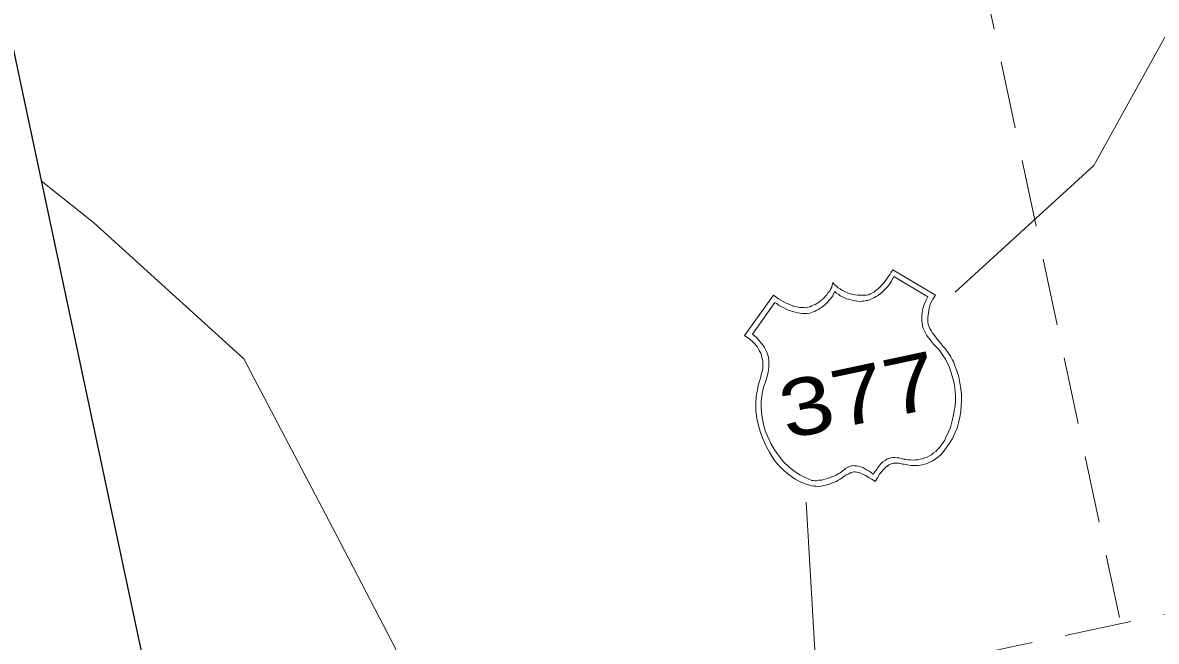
# Model space of a CAD drawing. Extents: x 2357218 to 2371708, y 6973728 to 6980157.
# Drawn here: x 2357307.6 to 2357408.8, y 6974509.8 to 6974565 of the extents above; entities that cross this region are included whole.
import ezdxf

# ---------------------------------------------------------------- set-up
doc = ezdxf.new("R2010")
doc.units = 0
doc.header["$LTSCALE"] = 2
doc.linetypes.add('MEDIUM_DASHED', pattern=[4.5, 3, -1.5])
doc.layers.add('62', color=7, linetype='Continuous', lineweight=13)
doc.layers.add('63', color=7, linetype='Continuous', lineweight=13)

msp = doc.modelspace()

# ---------------------------------------------------------------- linework, layer by layer
at = {"layer": '62', "linetype": 'MEDIUM_DASHED'}
for p, q in [((2357366.864, 6974693.567), (2357405.498, 6974511.924)), ((2357321.423, 6974493.477), (2357761.192, 6974586.953))]:
    msp.add_line(p, q, dxfattribs=at)
at = {"layer": '62'}
msp.add_line((2357403.224, 6974552.273), (2357390.835, 6974540.968), dxfattribs=at)
at = {"layer": '62', "lineweight": 25}
msp.add_lwpolyline([(2357242.867, 6974863.05), (2357339.603, 6974407.945), (2357779.37, 6974501.42), (2357682.634, 6974956.528)], dxfattribs=at)
at = {"layer": '62'}
for points in [[(2357432.423, 6974601.035), (2357426.152, 6974591.262), (2357421.824, 6974582.844), (2357411.809, 6974567.829), (2357403.224, 6974552.273)], [(2357309.219, 6974550.9), (2357313.892, 6974547.2), (2357327.315, 6974535.032), (2357335.518, 6974519.384), (2357342.091, 6974506.75), (2357351.934, 6974500.263), (2357369.659, 6974490.04), (2357379.731, 6974485.624), (2357395.823, 6974478.418), (2357410.579, 6974464.416)], [(2357372.035, 6974537.087), (2357374.604, 6974540.692), (2357374.818, 6974540.552), (2357375.062, 6974540.374), (2357375.271, 6974540.259), (2357375.48, 6974540.141), (2357375.689, 6974540.024), (2357375.916, 6974539.934), (2357376.12, 6974539.841), (2357376.325, 6974539.745), (2357376.519, 6974539.694), (2357376.714, 6974539.645), (2357376.928, 6974539.599), (2357377.115, 6974539.593), (2357377.322, 6974539.591), (2357377.486, 6974539.58), (2357377.684, 6974539.62), (2357377.882, 6974539.663), (2357378.005, 6974539.736), (2357378.15, 6974539.813), (2357378.322, 6974539.873), (2357378.489, 6974539.953), (2357378.646, 6974540.078), (2357378.808, 6974540.182), (2357378.942, 6974540.301), (2357379.1, 6974540.426), (2357379.249, 6974540.598), (2357379.38, 6974540.742), (2357379.5, 6974540.928), (2357379.631, 6974541.071), (2357379.732, 6974541.252), (2357379.806, 6974541.429), (2357379.857, 6974541.623), (2357379.91, 6974541.819), (2357380.057, 6974541.665), (2357380.225, 6974541.518), (2357380.372, 6974541.365), (2357380.557, 6974541.266), (2357380.721, 6974541.139), (2357380.924, 6974541.046), (2357381.129, 6974540.95), (2357381.305, 6974540.873), (2357381.501, 6974540.824), (2357381.703, 6974540.751), (2357381.914, 6974540.728), (2357382.103, 6974540.697), (2357382.335, 6974540.702), (2357382.497, 6974540.689), (2357382.725, 6974540.693), (2357382.928, 6974540.712), (2357383.082, 6974540.745), (2357383.252, 6974540.805), (2357383.397, 6974540.88), (2357383.589, 6974540.968), (2357383.723, 6974541.088), (2357383.88, 6974541.214), (2357384.016, 6974541.335), (2357384.169, 6974541.483), (2357384.298, 6974541.625), (2357384.469, 6974541.8), (2357384.596, 6974541.965), (2357384.737, 6974542.154), (2357384.861, 6974542.343), (2357385.019, 6974542.561), (2357385.12, 6974542.742), (2357385.258, 6974542.955), (2357389.073, 6974540.708), (2357388.851, 6974540.338), (2357388.635, 6974539.949), (2357388.515, 6974539.531), (2357388.443, 6974539.123), (2357388.389, 6974538.721), (2357388.398, 6974538.354), (2357388.432, 6974538.086), (2357388.502, 6974537.871), (2357388.557, 6974537.721), (2357388.687, 6974537.541), (2357388.788, 6974537.381), (2357388.924, 6974537.177), (2357389.082, 6974536.979), (2357389.24, 6974536.784), (2357389.401, 6974536.566), (2357389.584, 6974536.351), (2357389.772, 6974536.113), (2357389.956, 6974535.901), (2357390.148, 6974535.641), (2357390.309, 6974535.424), (2357390.448, 6974535.201), (2357390.571, 6974534.951), (2357390.71, 6974534.726), (2357390.784, 6974534.488), (2357390.995, 6974533.937), (2357391.15, 6974533.417), (2357391.262, 6974532.889), (2357391.33, 6974532.352), (2357391.394, 6974531.835), (2357391.39, 6974531.306), (2357391.379, 6974530.822), (2357391.327, 6974530.303), (2357391.252, 6974529.803), (2357391.129, 6974529.294)], [(2357390.148, 6974528.28), (2357390.272, 6974528.562), (2357390.409, 6974528.89), (2357390.515, 6974529.258), (2357390.605, 6974529.597), (2357390.679, 6974530.005), (2357390.755, 6974530.411), (2357390.828, 6974530.817), (2357390.85, 6974531.261), (2357390.849, 6974531.697), (2357390.82, 6974532.151), (2357390.788, 6974532.628), (2357390.688, 6974533.089), (2357390.544, 6974533.565), (2357390.408, 6974533.973), (2357390.288, 6974534.338), (2357390.125, 6974534.671), (2357389.967, 6974534.982), (2357389.766, 6974535.284), (2357389.572, 6974535.543), (2357389.399, 6974535.806), (2357389.191, 6974536.038), (2357388.958, 6974536.264), (2357388.8, 6974536.459), (2357388.618, 6974536.673), (2357388.457, 6974536.893), (2357388.294, 6974537.112), (2357388.177, 6974537.342), (2357388.059, 6974537.57), (2357387.958, 6974537.824), (2357387.893, 6974538.132), (2357387.867, 6974538.474), (2357387.864, 6974538.817), (2357387.881, 6974539.167), (2357387.944, 6974539.524), (2357388.075, 6974539.873), (2357388.213, 6974540.203), (2357388.395, 6974540.54), (2357385.363, 6974542.357), (2357385.246, 6974542.148), (2357385.146, 6974541.965), (2357385.026, 6974541.78), (2357384.904, 6974541.593), (2357384.758, 6974541.423), (2357384.608, 6974541.253), (2357384.457, 6974541.107), (2357384.302, 6974540.96), (2357384.123, 6974540.83), (2357383.971, 6974540.682), (2357383.786, 6974540.572), (2357383.642, 6974540.495), (2357383.459, 6974540.389), (2357383.309, 6974540.333), (2357383.18, 6974540.284), (2357383.03, 6974540.229), (2357382.874, 6974540.216), (2357382.674, 6974540.174), (2357382.493, 6974540.16), (2357382.312, 6974540.145), (2357382.101, 6974540.168), (2357381.932, 6974540.202), (2357381.72, 6974540.227), (2357381.525, 6974540.278), (2357381.352, 6974540.333), (2357381.134, 6974540.378), (2357380.958, 6974540.455), (2357380.775, 6974540.555), (2357380.576, 6974540.628), (2357380.434, 6974540.758), (2357380.247, 6974540.878), (2357380.076, 6974541.026), (2357379.982, 6974540.823), (2357379.906, 6974540.646), (2357379.775, 6974540.501), (2357379.672, 6974540.341), (2357379.557, 6974540.227), (2357379.449, 6974540.089), (2357379.295, 6974539.94), (2357379.202, 6974539.829), (2357379.042, 6974539.726), (2357378.906, 6974539.605), (2357378.763, 6974539.527), (2357378.622, 6974539.429), (2357378.47, 6974539.375), (2357378.334, 6974539.276), (2357378.163, 6974539.215), (2357378.013, 6974539.161), (2357377.841, 6974539.103), (2357377.62, 6974539.056), (2357377.435, 6974539.062), (2357377.206, 6974539.06), (2357376.995, 6974539.083), (2357376.755, 6974539.124), (2357376.539, 6974539.171), (2357376.339, 6974539.244), (2357376.116, 6974539.312), (2357375.871, 6974539.397), (2357375.67, 6974539.469), (2357375.483, 6974539.589), (2357375.252, 6974539.703), (2357375.065, 6974539.822)], [(2357374.742, 6974540.054), (2357372.723, 6974537.21), (2357373.083, 6974536.919), (2357373.361, 6974536.585), (2357373.602, 6974536.314), (2357373.801, 6974536.036), (2357373.959, 6974535.725), (2357374.067, 6974535.425), (2357374.169, 6974535.169), (2357374.187, 6974534.874), (2357374.202, 6974534.578), (2357374.192, 6974534.3), (2357374.165, 6974533.992), (2357374.112, 6974533.706), (2357374.052, 6974533.44), (2357373.953, 6974533.143), (2357373.854, 6974532.87), (2357373.754, 6974532.572), (2357373.59, 6974531.937), (2357373.523, 6974531.281), (2357373.495, 6974530.653), (2357373.569, 6974529.98), (2357373.687, 6974529.316), (2357373.845, 6974528.679), (2357374.095, 6974528.044), (2357374.378, 6974527.46), (2357374.708, 6974526.888), (2357375.106, 6974526.327), (2357375.506, 6974525.837), (2357375.973, 6974525.383), (2357376.445, 6974525.001), (2357376.955, 6974524.65), (2357377.495, 6974524.397), (2357378.047, 6974524.168), (2357378.163, 6974524.17), (2357378.288, 6974524.128), (2357378.444, 6974524.138), (2357378.622, 6974524.174), (2357378.779, 6974524.185), (2357378.938, 6974524.197), (2357379.116, 6974524.235), (2357379.307, 6974524.299), (2357379.481, 6974524.358), (2357379.655, 6974524.395), (2357379.823, 6974524.477), (2357379.993, 6974524.537), (2357380.16, 6974524.617), (2357380.305, 6974524.695), (2357380.445, 6974524.794), (2357380.572, 6974524.842), (2357380.707, 6974524.965), (2357380.826, 6974525.059), (2357380.944, 6974525.152), (2357381.063, 6974525.245), (2357381.229, 6974525.327), (2357381.334, 6974525.374), (2357381.479, 6974525.45), (2357381.655, 6974525.487), (2357381.817, 6974525.477), (2357382.026, 6974525.474), (2357382.216, 6974525.445), (2357382.394, 6974525.368), (2357382.643, 6974525.284), (2357382.909, 6974525.11), (2357383.218, 6974524.946), (2357383.517, 6974524.734), (2357383.765, 6974525.085), (2357383.978, 6974525.384), (2357384.159, 6974525.607), (2357384.369, 6974525.812), (2357384.57, 6974525.946), (2357384.732, 6974526.049), (2357384.922, 6974526.135), (2357385.119, 6974526.179), (2357385.297, 6974526.216), (2357385.46, 6974526.204), (2357385.65, 6974526.175), (2357385.835, 6974526.169), (2357386.03, 6974526.119), (2357386.225, 6974526.066), (2357386.41, 6974526.061), (2357386.631, 6974525.993), (2357386.84, 6974525.992), (2357387.075, 6974525.971), (2357387.277, 6974525.991), (2357387.478, 6974526.011), (2357387.699, 6974526.059), (2357387.92, 6974526.105), (2357388.115, 6974526.169), (2357388.329, 6974526.239), (2357388.534, 6974526.35), (2357388.724, 6974526.438), (2357388.894, 6974526.613), (2357389.094, 6974526.747), (2357389.244, 6974526.916), (2357389.435, 6974527.094), (2357389.595, 6974527.314), (2357389.751, 6974527.552), (2357389.896, 6974527.746), (2357389.999, 6974528.02), (2357390.148, 6974528.28)], [(2357375.065, 6974539.822), (2357374.901, 6974539.95), (2357374.742, 6974540.054)], [(2357372.859, 6974536.455), (2357372.495, 6974536.77), (2357372.035, 6974537.087)], [(2357391.129, 6974529.294), (2357390.999, 6974528.829), (2357390.795, 6974528.373), (2357390.596, 6974527.917), (2357390.316, 6974527.49), (2357390.039, 6974527.063), (2357389.736, 6974526.653), (2357389.547, 6974526.451), (2357389.373, 6974526.3), (2357389.154, 6974526.139), (2357388.954, 6974526.002), (2357388.775, 6974525.874), (2357388.558, 6974525.805), (2357388.33, 6974525.687), (2357388.137, 6974525.622), (2357387.922, 6974525.555), (2357387.697, 6974525.528), (2357387.494, 6974525.51), (2357387.292, 6974525.489), (2357387.057, 6974525.509), (2357386.898, 6974525.498), (2357386.686, 6974525.52), (2357386.491, 6974525.573), (2357386.323, 6974525.606), (2357386.14, 6974525.611), (2357385.966, 6974525.667), (2357385.8, 6974525.7), (2357385.638, 6974525.69), (2357385.475, 6974525.7), (2357385.289, 6974525.708), (2357385.117, 6974525.649), (2357384.951, 6974525.567), (2357384.789, 6974525.464), (2357384.613, 6974525.311), (2357384.46, 6974525.162), (2357384.257, 6974524.935), (2357384.073, 6974524.713), (2357383.91, 6974524.402), (2357383.683, 6974524.056), (2357383.387, 6974524.267), (2357383.097, 6974524.436), (2357382.853, 6974524.613), (2357382.625, 6974524.704), (2357382.417, 6974524.821), (2357382.224, 6974524.872), (2357382.055, 6974524.906), (2357381.891, 6974524.917), (2357381.777, 6974524.916), (2357381.601, 6974524.879), (2357381.49, 6974524.853), (2357381.351, 6974524.756), (2357381.223, 6974524.704), (2357381.096, 6974524.656), (2357380.962, 6974524.535), (2357380.813, 6974524.458), (2357380.72, 6974524.368), (2357380.553, 6974524.288), (2357380.391, 6974524.182), (2357380.231, 6974524.08), (2357380.036, 6974524.014), (2357379.864, 6974523.958), (2357379.679, 6974523.849), (2357379.488, 6974523.785), (2357379.267, 6974523.737), (2357379.091, 6974523.701), (2357378.87, 6974523.654), (2357378.623, 6974523.622), (2357378.411, 6974523.649), (2357378.183, 6974523.645), (2357377.938, 6974523.708), (2357377.696, 6974523.771), (2357377.123, 6974523.972), (2357376.549, 6974524.289), (2357376.011, 6974524.656), (2357375.508, 6974525.078), (2357375.039, 6974525.553), (2357374.637, 6974526.042), (2357374.284, 6974526.612), (2357373.951, 6974527.207), (2357373.684, 6974527.819), (2357373.459, 6974528.437), (2357373.259, 6974529.063), (2357373.123, 6974529.701), (2357373.047, 6974530.374), (2357373.032, 6974530.993), (2357373.073, 6974531.668), (2357373.173, 6974532.265), (2357373.217, 6974532.502), (2357373.274, 6974532.768), (2357373.359, 6974533.016), (2357373.464, 6974533.291), (2357373.517, 6974533.58), (2357373.592, 6974533.872), (2357373.664, 6974534.188), (2357373.67, 6974534.487), (2357373.647, 6974534.807), (2357373.577, 6974535.136), (2357373.508, 6974535.468), (2357373.327, 6974535.774), (2357373.142, 6974536.104), (2357372.859, 6974536.455)], [(2357377.519, 6974522.215), (2357378.302, 6974509.018), (2357377.771, 6974495.492), (2357368.736, 6974481.608), (2357356.967, 6974466.526), (2357344.304, 6974446.557), (2357333.83, 6974435.105)]]:
    msp.add_lwpolyline(points, dxfattribs=at)
at = {"layer": '63', "linetype": 'MEDIUM_DASHED'}
for p, q in [((2357366.864, 6974693.567), (2357405.498, 6974511.924)), ((2357321.423, 6974493.477), (2357761.192, 6974586.953))]:
    msp.add_line(p, q, dxfattribs=at)
at = {"layer": '63'}
msp.add_line((2357403.224, 6974552.273), (2357390.835, 6974540.968), dxfattribs=at)
at = {"layer": '63', "lineweight": 25}
msp.add_lwpolyline([(2357242.867, 6974863.05), (2357339.603, 6974407.945), (2357779.37, 6974501.42), (2357682.634, 6974956.528)], dxfattribs=at)
at = {"layer": '63'}
for points in [[(2357432.423, 6974601.035), (2357426.152, 6974591.262), (2357421.824, 6974582.844), (2357411.809, 6974567.829), (2357403.224, 6974552.273)], [(2357309.219, 6974550.9), (2357313.892, 6974547.2), (2357327.315, 6974535.032), (2357335.518, 6974519.384), (2357342.091, 6974506.75), (2357351.934, 6974500.263), (2357369.659, 6974490.04), (2357379.731, 6974485.624), (2357395.823, 6974478.418), (2357410.579, 6974464.416)], [(2357372.035, 6974537.087), (2357374.604, 6974540.692), (2357374.818, 6974540.552), (2357375.062, 6974540.374), (2357375.271, 6974540.259), (2357375.48, 6974540.141), (2357375.689, 6974540.024), (2357375.916, 6974539.934), (2357376.12, 6974539.841), (2357376.325, 6974539.745), (2357376.519, 6974539.694), (2357376.714, 6974539.645), (2357376.928, 6974539.599), (2357377.115, 6974539.593), (2357377.322, 6974539.591), (2357377.486, 6974539.58), (2357377.684, 6974539.62), (2357377.882, 6974539.663), (2357378.005, 6974539.736), (2357378.15, 6974539.813), (2357378.322, 6974539.873), (2357378.489, 6974539.953), (2357378.646, 6974540.078), (2357378.808, 6974540.182), (2357378.942, 6974540.301), (2357379.1, 6974540.426), (2357379.249, 6974540.598), (2357379.38, 6974540.742), (2357379.5, 6974540.928), (2357379.631, 6974541.071), (2357379.732, 6974541.252), (2357379.806, 6974541.429), (2357379.857, 6974541.623), (2357379.91, 6974541.819), (2357380.057, 6974541.665), (2357380.225, 6974541.518), (2357380.372, 6974541.365), (2357380.557, 6974541.266), (2357380.721, 6974541.139), (2357380.924, 6974541.046), (2357381.129, 6974540.95), (2357381.305, 6974540.873), (2357381.501, 6974540.824), (2357381.703, 6974540.751), (2357381.914, 6974540.728), (2357382.103, 6974540.697), (2357382.335, 6974540.702), (2357382.497, 6974540.689), (2357382.725, 6974540.693), (2357382.928, 6974540.712), (2357383.082, 6974540.745), (2357383.252, 6974540.805), (2357383.397, 6974540.88), (2357383.589, 6974540.968), (2357383.723, 6974541.088), (2357383.88, 6974541.214), (2357384.016, 6974541.335), (2357384.169, 6974541.483), (2357384.298, 6974541.625), (2357384.469, 6974541.8), (2357384.596, 6974541.965), (2357384.737, 6974542.154), (2357384.861, 6974542.343), (2357385.019, 6974542.561), (2357385.12, 6974542.742), (2357385.258, 6974542.955), (2357389.073, 6974540.708), (2357388.851, 6974540.338), (2357388.635, 6974539.949), (2357388.515, 6974539.531), (2357388.443, 6974539.123), (2357388.389, 6974538.721), (2357388.398, 6974538.354), (2357388.432, 6974538.086), (2357388.502, 6974537.871), (2357388.557, 6974537.721), (2357388.687, 6974537.541), (2357388.788, 6974537.381), (2357388.924, 6974537.177), (2357389.082, 6974536.979), (2357389.24, 6974536.784), (2357389.401, 6974536.566), (2357389.584, 6974536.351), (2357389.772, 6974536.113), (2357389.956, 6974535.901), (2357390.148, 6974535.641), (2357390.309, 6974535.424), (2357390.448, 6974535.201), (2357390.571, 6974534.951), (2357390.71, 6974534.726), (2357390.784, 6974534.488), (2357390.995, 6974533.937), (2357391.15, 6974533.417), (2357391.262, 6974532.889), (2357391.33, 6974532.352), (2357391.394, 6974531.835), (2357391.39, 6974531.306), (2357391.379, 6974530.822), (2357391.327, 6974530.303), (2357391.252, 6974529.803), (2357391.129, 6974529.294)], [(2357390.148, 6974528.28), (2357390.272, 6974528.562), (2357390.409, 6974528.89), (2357390.515, 6974529.258), (2357390.605, 6974529.597), (2357390.679, 6974530.005), (2357390.755, 6974530.411), (2357390.828, 6974530.817), (2357390.85, 6974531.261), (2357390.849, 6974531.697), (2357390.82, 6974532.151), (2357390.788, 6974532.628), (2357390.688, 6974533.089), (2357390.544, 6974533.565), (2357390.408, 6974533.973), (2357390.288, 6974534.338), (2357390.125, 6974534.671), (2357389.967, 6974534.982), (2357389.766, 6974535.284), (2357389.572, 6974535.543), (2357389.399, 6974535.806), (2357389.191, 6974536.038), (2357388.958, 6974536.264), (2357388.8, 6974536.459), (2357388.618, 6974536.673), (2357388.457, 6974536.893), (2357388.294, 6974537.112), (2357388.177, 6974537.342), (2357388.059, 6974537.57), (2357387.958, 6974537.824), (2357387.893, 6974538.132), (2357387.867, 6974538.474), (2357387.864, 6974538.817), (2357387.881, 6974539.167), (2357387.944, 6974539.524), (2357388.075, 6974539.873), (2357388.213, 6974540.203), (2357388.395, 6974540.54), (2357385.363, 6974542.357), (2357385.246, 6974542.148), (2357385.146, 6974541.965), (2357385.026, 6974541.78), (2357384.904, 6974541.593), (2357384.758, 6974541.423), (2357384.608, 6974541.253), (2357384.457, 6974541.107), (2357384.302, 6974540.96), (2357384.123, 6974540.83), (2357383.971, 6974540.682), (2357383.786, 6974540.572), (2357383.642, 6974540.495), (2357383.459, 6974540.389), (2357383.309, 6974540.333), (2357383.18, 6974540.284), (2357383.03, 6974540.229), (2357382.874, 6974540.216), (2357382.674, 6974540.174), (2357382.493, 6974540.16), (2357382.312, 6974540.145), (2357382.101, 6974540.168), (2357381.932, 6974540.202), (2357381.72, 6974540.227), (2357381.525, 6974540.278), (2357381.352, 6974540.333), (2357381.134, 6974540.378), (2357380.958, 6974540.455), (2357380.775, 6974540.555), (2357380.576, 6974540.628), (2357380.434, 6974540.758), (2357380.247, 6974540.878), (2357380.076, 6974541.026), (2357379.982, 6974540.823), (2357379.906, 6974540.646), (2357379.775, 6974540.501), (2357379.672, 6974540.341), (2357379.557, 6974540.227), (2357379.449, 6974540.089), (2357379.295, 6974539.94), (2357379.202, 6974539.829), (2357379.042, 6974539.726), (2357378.906, 6974539.605), (2357378.763, 6974539.527), (2357378.622, 6974539.429), (2357378.47, 6974539.375), (2357378.334, 6974539.276), (2357378.163, 6974539.215), (2357378.013, 6974539.161), (2357377.841, 6974539.103), (2357377.62, 6974539.056), (2357377.435, 6974539.062), (2357377.206, 6974539.06), (2357376.995, 6974539.083), (2357376.755, 6974539.124), (2357376.539, 6974539.171), (2357376.339, 6974539.244), (2357376.116, 6974539.312), (2357375.871, 6974539.397), (2357375.67, 6974539.469), (2357375.483, 6974539.589), (2357375.252, 6974539.703), (2357375.065, 6974539.822)], [(2357374.742, 6974540.054), (2357372.723, 6974537.21), (2357373.083, 6974536.919), (2357373.361, 6974536.585), (2357373.602, 6974536.314), (2357373.801, 6974536.036), (2357373.959, 6974535.725), (2357374.067, 6974535.425), (2357374.169, 6974535.169), (2357374.187, 6974534.874), (2357374.202, 6974534.578), (2357374.192, 6974534.3), (2357374.165, 6974533.992), (2357374.112, 6974533.706), (2357374.052, 6974533.44), (2357373.953, 6974533.143), (2357373.854, 6974532.87), (2357373.754, 6974532.572), (2357373.59, 6974531.937), (2357373.523, 6974531.281), (2357373.495, 6974530.653), (2357373.569, 6974529.98), (2357373.687, 6974529.316), (2357373.845, 6974528.679), (2357374.095, 6974528.044), (2357374.378, 6974527.46), (2357374.708, 6974526.888), (2357375.106, 6974526.327), (2357375.506, 6974525.837), (2357375.973, 6974525.383), (2357376.445, 6974525.001), (2357376.955, 6974524.65), (2357377.495, 6974524.397), (2357378.047, 6974524.168), (2357378.163, 6974524.17), (2357378.288, 6974524.128), (2357378.444, 6974524.138), (2357378.622, 6974524.174), (2357378.779, 6974524.185), (2357378.938, 6974524.197), (2357379.116, 6974524.235), (2357379.307, 6974524.299), (2357379.481, 6974524.358), (2357379.655, 6974524.395), (2357379.823, 6974524.477), (2357379.993, 6974524.537), (2357380.16, 6974524.617), (2357380.305, 6974524.695), (2357380.445, 6974524.794), (2357380.572, 6974524.842), (2357380.707, 6974524.965), (2357380.826, 6974525.059), (2357380.944, 6974525.152), (2357381.063, 6974525.245), (2357381.229, 6974525.327), (2357381.334, 6974525.374), (2357381.479, 6974525.45), (2357381.655, 6974525.487), (2357381.817, 6974525.477), (2357382.026, 6974525.474), (2357382.216, 6974525.445), (2357382.394, 6974525.368), (2357382.643, 6974525.284), (2357382.909, 6974525.11), (2357383.218, 6974524.946), (2357383.517, 6974524.734), (2357383.765, 6974525.085), (2357383.978, 6974525.384), (2357384.159, 6974525.607), (2357384.369, 6974525.812), (2357384.57, 6974525.946), (2357384.732, 6974526.049), (2357384.922, 6974526.135), (2357385.119, 6974526.179), (2357385.297, 6974526.216), (2357385.46, 6974526.204), (2357385.65, 6974526.175), (2357385.835, 6974526.169), (2357386.03, 6974526.119), (2357386.225, 6974526.066), (2357386.41, 6974526.061), (2357386.631, 6974525.993), (2357386.84, 6974525.992), (2357387.075, 6974525.971), (2357387.277, 6974525.991), (2357387.478, 6974526.011), (2357387.699, 6974526.059), (2357387.92, 6974526.105), (2357388.115, 6974526.169), (2357388.329, 6974526.239), (2357388.534, 6974526.35), (2357388.724, 6974526.438), (2357388.894, 6974526.613), (2357389.094, 6974526.747), (2357389.244, 6974526.916), (2357389.435, 6974527.094), (2357389.595, 6974527.314), (2357389.751, 6974527.552), (2357389.896, 6974527.746), (2357389.999, 6974528.02), (2357390.148, 6974528.28)], [(2357375.065, 6974539.822), (2357374.901, 6974539.95), (2357374.742, 6974540.054)], [(2357372.859, 6974536.455), (2357372.495, 6974536.77), (2357372.035, 6974537.087)], [(2357391.129, 6974529.294), (2357390.999, 6974528.829), (2357390.795, 6974528.373), (2357390.596, 6974527.917), (2357390.316, 6974527.49), (2357390.039, 6974527.063), (2357389.736, 6974526.653), (2357389.547, 6974526.451), (2357389.373, 6974526.3), (2357389.154, 6974526.139), (2357388.954, 6974526.002), (2357388.775, 6974525.874), (2357388.558, 6974525.805), (2357388.33, 6974525.687), (2357388.137, 6974525.622), (2357387.922, 6974525.555), (2357387.697, 6974525.528), (2357387.494, 6974525.51), (2357387.292, 6974525.489), (2357387.057, 6974525.509), (2357386.898, 6974525.498), (2357386.686, 6974525.52), (2357386.491, 6974525.573), (2357386.323, 6974525.606), (2357386.14, 6974525.611), (2357385.966, 6974525.667), (2357385.8, 6974525.7), (2357385.638, 6974525.69), (2357385.475, 6974525.7), (2357385.289, 6974525.708), (2357385.117, 6974525.649), (2357384.951, 6974525.567), (2357384.789, 6974525.464), (2357384.613, 6974525.311), (2357384.46, 6974525.162), (2357384.257, 6974524.935), (2357384.073, 6974524.713), (2357383.91, 6974524.402), (2357383.683, 6974524.056), (2357383.387, 6974524.267), (2357383.097, 6974524.436), (2357382.853, 6974524.613), (2357382.625, 6974524.704), (2357382.417, 6974524.821), (2357382.224, 6974524.872), (2357382.055, 6974524.906), (2357381.891, 6974524.917), (2357381.777, 6974524.916), (2357381.601, 6974524.879), (2357381.49, 6974524.853), (2357381.351, 6974524.756), (2357381.223, 6974524.704), (2357381.096, 6974524.656), (2357380.962, 6974524.535), (2357380.813, 6974524.458), (2357380.72, 6974524.368), (2357380.553, 6974524.288), (2357380.391, 6974524.182), (2357380.231, 6974524.08), (2357380.036, 6974524.014), (2357379.864, 6974523.958), (2357379.679, 6974523.849), (2357379.488, 6974523.785), (2357379.267, 6974523.737), (2357379.091, 6974523.701), (2357378.87, 6974523.654), (2357378.623, 6974523.622), (2357378.411, 6974523.649), (2357378.183, 6974523.645), (2357377.938, 6974523.708), (2357377.696, 6974523.771), (2357377.123, 6974523.972), (2357376.549, 6974524.289), (2357376.011, 6974524.656), (2357375.508, 6974525.078), (2357375.039, 6974525.553), (2357374.637, 6974526.042), (2357374.284, 6974526.612), (2357373.951, 6974527.207), (2357373.684, 6974527.819), (2357373.459, 6974528.437), (2357373.259, 6974529.063), (2357373.123, 6974529.701), (2357373.047, 6974530.374), (2357373.032, 6974530.993), (2357373.073, 6974531.668), (2357373.173, 6974532.265), (2357373.217, 6974532.502), (2357373.274, 6974532.768), (2357373.359, 6974533.016), (2357373.464, 6974533.291), (2357373.517, 6974533.58), (2357373.592, 6974533.872), (2357373.664, 6974534.188), (2357373.67, 6974534.487), (2357373.647, 6974534.807), (2357373.577, 6974535.136), (2357373.508, 6974535.468), (2357373.327, 6974535.774), (2357373.142, 6974536.104), (2357372.859, 6974536.455)], [(2357377.519, 6974522.215), (2357378.302, 6974509.018), (2357377.771, 6974495.492), (2357368.736, 6974481.608), (2357356.967, 6974466.526), (2357344.304, 6974446.557), (2357333.83, 6974435.105)]]:
    msp.add_lwpolyline(points, dxfattribs=at)

# ---------------------------------------------------------------- texts
at = {"layer": '62', "width": 1.25}
msp.add_text('377', height=5.099, rotation=12, dxfattribs=at).set_placement((2357375.775, 6974527.826))
at = {"layer": '63', "width": 1.25}
msp.add_text('377', height=5.099, rotation=12, dxfattribs=at).set_placement((2357375.775, 6974527.826))

doc.saveas('drawing.dxf')
